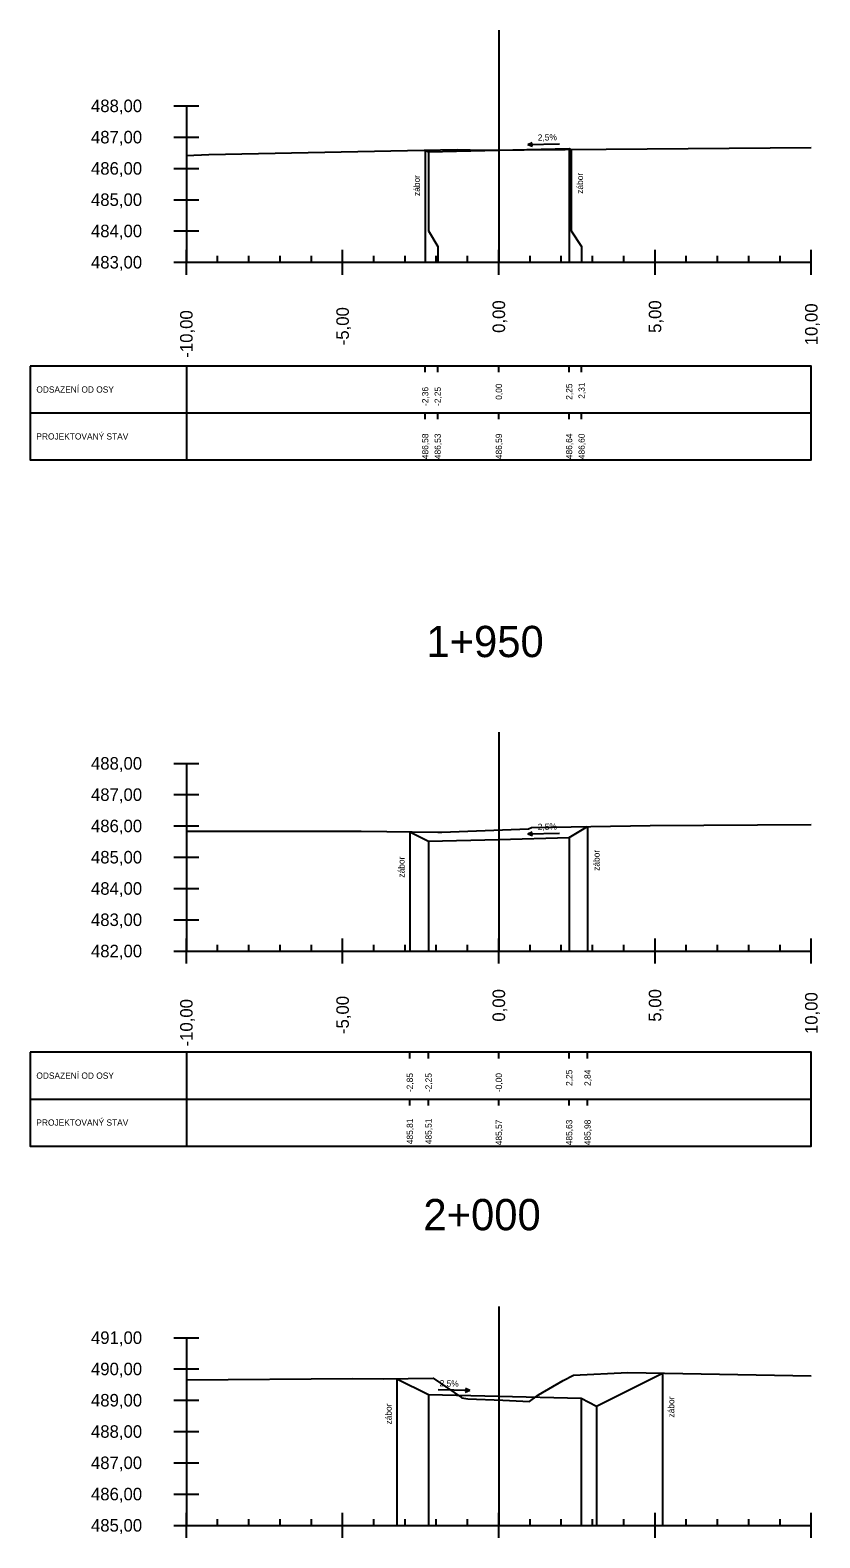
# Model space of a CAD drawing. Extents: x -631407 to -631215, y -1089700 to -1088598.
# Drawn here: x -631285.2 to -631259.93, y -1088856.74 to -1088808.54 of the extents above; entities that cross this region are included whole.
import ezdxf

# ---------------------------------------------------------------- set-up
doc = ezdxf.new("R2010")
doc.units = 0
for name, color, linetype in [('59', 7, 'Continuous'), ('NIVELETA_VYSKY', 7, 'Continuous'), ('REZ_BODY', 7, 'Continuous'), ('REZ_ODSTUPY', 7, 'Continuous'), ('REZ_POPIS', 7, 'Continuous'), ('REZ_RAMY', 7, 'Continuous'), ('REZ_STANICENI', 7, 'Continuous'), ('REZ_SVISLE', 7, 'Continuous'), ('REZ_TENKA', 7, 'Continuous'), ('REZ_TLUSTA', 7, 'Continuous'), ('TABULKA_POPIS', 7, 'Continuous'), ('TEREN', 7, 'Continuous'), ('zábor', 7, 'Continuous')]:
    doc.layers.add(name, color=color, linetype=linetype)

msp = doc.modelspace()

# ---------------------------------------------------------------- linework, layer by layer
at = {"layer": '59'}
for p, q in [((-631280.602, -1088810.959), (-631279.802, -1088810.959)), ((-631280.202, -1088810.959), (-631280.202, -1088815.959)), ((-631280.602, -1088811.959), (-631279.802, -1088811.959)), ((-631280.602, -1088812.959), (-631279.802, -1088812.959)), ((-631280.602, -1088813.959), (-631279.802, -1088813.959)), ((-631280.602, -1088814.959), (-631279.802, -1088814.959)), ((-631280.602, -1088815.959), (-631279.802, -1088815.959)), ((-631280.602, -1088831.981), (-631279.802, -1088831.981)), ((-631280.202, -1088831.981), (-631280.202, -1088837.981)), ((-631280.602, -1088832.981), (-631279.802, -1088832.981)), ((-631280.602, -1088833.981), (-631279.802, -1088833.981)), ((-631280.602, -1088834.981), (-631279.802, -1088834.981)), ((-631280.602, -1088835.981), (-631279.802, -1088835.981)), ((-631280.602, -1088836.981), (-631279.802, -1088836.981)), ((-631280.602, -1088837.981), (-631279.802, -1088837.981)), ((-631280.602, -1088850.343), (-631279.802, -1088850.343)), ((-631280.202, -1088850.343), (-631280.202, -1088856.343)), ((-631280.602, -1088851.343), (-631279.802, -1088851.343)), ((-631280.602, -1088852.343), (-631279.802, -1088852.343)), ((-631280.602, -1088853.343), (-631279.802, -1088853.343)), ((-631280.602, -1088854.343), (-631279.802, -1088854.343)), ((-631280.602, -1088855.343), (-631279.802, -1088855.343)), ((-631280.602, -1088856.343), (-631279.802, -1088856.343))]:
    msp.add_line(p, q, dxfattribs=at)
at = {"layer": 'REZ_RAMY'}
for p, q in [((-631285.202, -1088819.278), (-631285.202, -1088822.278)), ((-631280.202, -1088819.278), (-631280.202, -1088822.278)), ((-631272.558, -1088819.478), (-631272.558, -1088819.278)), ((-631272.158, -1088819.478), (-631272.158, -1088819.278)), ((-631270.202, -1088819.478), (-631270.202, -1088819.278)), ((-631267.952, -1088819.478), (-631267.952, -1088819.278)), ((-631267.552, -1088819.478), (-631267.552, -1088819.278)), ((-631285.202, -1088820.778), (-631260.202, -1088820.778)), ((-631272.558, -1088820.978), (-631272.558, -1088820.778)), ((-631272.158, -1088820.978), (-631272.158, -1088820.778)), ((-631270.202, -1088820.978), (-631270.202, -1088820.778)), ((-631267.952, -1088820.978), (-631267.952, -1088820.778)), ((-631267.552, -1088820.978), (-631267.552, -1088820.778)), ((-631285.202, -1088841.215), (-631285.202, -1088844.215)), ((-631280.202, -1088841.215), (-631280.202, -1088844.215)), ((-631273.05, -1088841.415), (-631273.05, -1088841.215)), ((-631272.452, -1088841.415), (-631272.452, -1088841.215)), ((-631270.202, -1088841.415), (-631270.202, -1088841.215)), ((-631267.952, -1088841.415), (-631267.952, -1088841.215)), ((-631267.362, -1088841.415), (-631267.362, -1088841.215)), ((-631285.202, -1088842.715), (-631260.202, -1088842.715)), ((-631273.05, -1088842.915), (-631273.05, -1088842.715)), ((-631272.452, -1088842.915), (-631272.452, -1088842.715)), ((-631270.202, -1088842.915), (-631270.202, -1088842.715)), ((-631267.952, -1088842.915), (-631267.952, -1088842.715)), ((-631267.362, -1088842.915), (-631267.362, -1088842.715))]:
    msp.add_line(p, q, dxfattribs=at)
for points in [[(-631285.202, -1088819.278), (-631285.202, -1088822.278), (-631260.202, -1088822.278), (-631260.202, -1088819.278)], [(-631285.202, -1088841.215), (-631285.202, -1088844.215), (-631260.202, -1088844.215), (-631260.202, -1088841.215)]]:
    msp.add_lwpolyline(points, close=True, dxfattribs=at)
at = {"layer": 'REZ_SVISLE'}
for points in [[(-631272.558, -1088812.377), (-631272.558, -1088814.959), (-631272.558, -1088815.459), (-631272.558, -1088815.959)], [(-631272.452, -1088812.43), (-631272.452, -1088814.959), (-631272.158, -1088815.459), (-631272.158, -1088815.959)], [(-631270.202, -1088812.374), (-631270.202, -1088814.959), (-631270.202, -1088815.459), (-631270.202, -1088815.959)], [(-631267.952, -1088812.318), (-631267.952, -1088814.959), (-631267.952, -1088815.459), (-631267.952, -1088815.959)], [(-631267.888, -1088812.356), (-631267.888, -1088814.959), (-631267.552, -1088815.459), (-631267.552, -1088815.959)], [(-631267.362, -1088834.002), (-631267.362, -1088836.981), (-631267.362, -1088837.481), (-631267.362, -1088837.981)], [(-631273.05, -1088834.169), (-631273.05, -1088836.981), (-631273.05, -1088837.481), (-631273.05, -1088837.981)], [(-631272.452, -1088834.469), (-631272.452, -1088836.981), (-631272.452, -1088837.481), (-631272.452, -1088837.981)], [(-631270.202, -1088834.412), (-631270.202, -1088836.981), (-631270.202, -1088837.481), (-631270.202, -1088837.981)], [(-631267.952, -1088834.356), (-631267.952, -1088836.981), (-631267.952, -1088837.481), (-631267.952, -1088837.981)], [(-631264.969, -1088851.481), (-631264.969, -1088855.343), (-631264.969, -1088855.843), (-631264.969, -1088856.343)], [(-631273.461, -1088851.655), (-631273.461, -1088855.343), (-631273.461, -1088855.843), (-631273.461, -1088856.343)], [(-631272.452, -1088852.16), (-631272.452, -1088855.343), (-631272.452, -1088855.843), (-631272.452, -1088856.343)], [(-631270.202, -1088852.216), (-631270.202, -1088855.343), (-631270.202, -1088855.843), (-631270.202, -1088856.343)], [(-631267.571, -1088852.282), (-631267.571, -1088855.343), (-631267.571, -1088855.843), (-631267.571, -1088856.343)], [(-631267.071, -1088852.532), (-631267.071, -1088855.343), (-631267.071, -1088855.843), (-631267.071, -1088856.343)]]:
    msp.add_lwpolyline(points, dxfattribs=at)
at = {"layer": 'REZ_TENKA'}
for p, q in [((-631279.202, -1088815.959), (-631279.202, -1088815.759)), ((-631278.202, -1088815.959), (-631278.202, -1088815.759)), ((-631277.202, -1088815.959), (-631277.202, -1088815.759)), ((-631276.202, -1088815.959), (-631276.202, -1088815.759)), ((-631274.202, -1088815.959), (-631274.202, -1088815.759)), ((-631273.202, -1088815.959), (-631273.202, -1088815.759)), ((-631272.202, -1088815.959), (-631272.202, -1088815.759)), ((-631271.202, -1088815.959), (-631271.202, -1088815.759)), ((-631269.202, -1088815.959), (-631269.202, -1088815.759)), ((-631268.202, -1088815.959), (-631268.202, -1088815.759)), ((-631267.202, -1088815.959), (-631267.202, -1088815.759)), ((-631266.202, -1088815.959), (-631266.202, -1088815.759)), ((-631264.202, -1088815.959), (-631264.202, -1088815.759)), ((-631263.202, -1088815.959), (-631263.202, -1088815.759)), ((-631262.202, -1088815.959), (-631262.202, -1088815.759)), ((-631261.202, -1088815.959), (-631261.202, -1088815.759)), ((-631279.202, -1088837.981), (-631279.202, -1088837.781)), ((-631278.202, -1088837.981), (-631278.202, -1088837.781)), ((-631277.202, -1088837.981), (-631277.202, -1088837.781)), ((-631276.202, -1088837.981), (-631276.202, -1088837.781)), ((-631274.202, -1088837.981), (-631274.202, -1088837.781)), ((-631273.202, -1088837.981), (-631273.202, -1088837.781)), ((-631272.202, -1088837.981), (-631272.202, -1088837.781)), ((-631271.202, -1088837.981), (-631271.202, -1088837.781)), ((-631269.202, -1088837.981), (-631269.202, -1088837.781)), ((-631268.202, -1088837.981), (-631268.202, -1088837.781)), ((-631267.202, -1088837.981), (-631267.202, -1088837.781)), ((-631266.202, -1088837.981), (-631266.202, -1088837.781)), ((-631264.202, -1088837.981), (-631264.202, -1088837.781)), ((-631263.202, -1088837.981), (-631263.202, -1088837.781)), ((-631262.202, -1088837.981), (-631262.202, -1088837.781)), ((-631261.202, -1088837.981), (-631261.202, -1088837.781)), ((-631279.202, -1088856.343), (-631279.202, -1088856.143)), ((-631278.202, -1088856.343), (-631278.202, -1088856.143)), ((-631277.202, -1088856.343), (-631277.202, -1088856.143)), ((-631276.202, -1088856.343), (-631276.202, -1088856.143)), ((-631274.202, -1088856.343), (-631274.202, -1088856.143)), ((-631273.202, -1088856.343), (-631273.202, -1088856.143)), ((-631272.202, -1088856.343), (-631272.202, -1088856.143)), ((-631271.202, -1088856.343), (-631271.202, -1088856.143)), ((-631269.202, -1088856.343), (-631269.202, -1088856.143)), ((-631268.202, -1088856.343), (-631268.202, -1088856.143)), ((-631267.202, -1088856.343), (-631267.202, -1088856.143)), ((-631266.202, -1088856.343), (-631266.202, -1088856.143)), ((-631264.202, -1088856.343), (-631264.202, -1088856.143)), ((-631263.202, -1088856.343), (-631263.202, -1088856.143)), ((-631262.202, -1088856.343), (-631262.202, -1088856.143)), ((-631261.202, -1088856.343), (-631261.202, -1088856.143))]:
    msp.add_line(p, q, dxfattribs=at)
at = {"layer": 'REZ_TLUSTA'}
for p, q in [((-631270.202, -1088808.539), (-631270.202, -1088815.959)), ((-631280.202, -1088816.359), (-631280.202, -1088815.559)), ((-631275.202, -1088816.359), (-631275.202, -1088815.559)), ((-631270.202, -1088816.359), (-631270.202, -1088815.559)), ((-631265.202, -1088816.359), (-631265.202, -1088815.559)), ((-631260.202, -1088816.359), (-631260.202, -1088815.559)), ((-631280.202, -1088815.959), (-631260.202, -1088815.959)), ((-631270.202, -1088830.981), (-631270.202, -1088837.981)), ((-631280.202, -1088838.381), (-631280.202, -1088837.581)), ((-631280.202, -1088837.981), (-631260.202, -1088837.981)), ((-631275.202, -1088838.381), (-631275.202, -1088837.581)), ((-631270.202, -1088838.381), (-631270.202, -1088837.581)), ((-631265.202, -1088838.381), (-631265.202, -1088837.581)), ((-631260.202, -1088838.381), (-631260.202, -1088837.581)), ((-631270.202, -1088849.343), (-631270.202, -1088856.343)), ((-631280.202, -1088856.743), (-631280.202, -1088855.943)), ((-631275.202, -1088856.743), (-631275.202, -1088855.943)), ((-631270.202, -1088856.743), (-631270.202, -1088855.943)), ((-631265.202, -1088856.743), (-631265.202, -1088855.943)), ((-631260.202, -1088856.743), (-631260.202, -1088855.943)), ((-631280.202, -1088856.343), (-631260.202, -1088856.343))]:
    msp.add_line(p, q, dxfattribs=at)
at = {"layer": 'TEREN'}
for points in [[(-631280.202, -1088812.543), (-631279.485, -1088812.517), (-631271.539, -1088812.356), (-631270.703, -1088812.379), (-631260.202, -1088812.292)], [(-631272.558, -1088812.377), (-631272.452, -1088812.43), (-631270.202, -1088812.374), (-631267.952, -1088812.318), (-631267.888, -1088812.356)], [(-631280.202, -1088834.15), (-631274.604, -1088834.154), (-631272.159, -1088834.178), (-631272.021, -1088834.176), (-631269.252, -1088834.078), (-631269.16, -1088834.037), (-631265.359, -1088833.964), (-631260.202, -1088833.938)], [(-631273.05, -1088834.169), (-631272.452, -1088834.469), (-631270.202, -1088834.412), (-631267.952, -1088834.356), (-631267.362, -1088834.002)], [(-631280.202, -1088851.694), (-631274.871, -1088851.648), (-631273.902, -1088851.662), (-631272.299, -1088851.639), (-631271.399, -1088852.26), (-631271.385, -1088852.267), (-631271.189, -1088852.299), (-631270.07, -1088852.34), (-631269.224, -1088852.379), (-631268.976, -1088852.202), (-631268.927, -1088852.171), (-631268.138, -1088851.709), (-631267.808, -1088851.541), (-631266.076, -1088851.461), (-631260.202, -1088851.567)], [(-631273.461, -1088851.655), (-631272.452, -1088852.16), (-631270.202, -1088852.216), (-631267.571, -1088852.282), (-631267.071, -1088852.532), (-631264.969, -1088851.481)]]:
    msp.add_lwpolyline(points, dxfattribs=at)
at = {"layer": 'zábor'}
for p, q in [((-631269.269, -1088812.194), (-631269.132, -1088812.13)), ((-631269.269, -1088812.194), (-631268.261, -1088812.169)), ((-631269.269, -1088812.194), (-631269.129, -1088812.252)), ((-631269.269, -1088834.233), (-631269.132, -1088834.168)), ((-631269.269, -1088834.233), (-631268.261, -1088834.208)), ((-631269.269, -1088834.233), (-631269.129, -1088834.291)), ((-631271.135, -1088852.037), (-631272.143, -1088852.012)), ((-631271.135, -1088852.037), (-631271.274, -1088852.095)), ((-631271.135, -1088852.037), (-631271.271, -1088851.972))]:
    msp.add_line(p, q, dxfattribs=at)

# ---------------------------------------------------------------- texts
at = {"layer": 'NIVELETA_VYSKY'}
for s, p in [('486,58', (-631272.458, -1088822.254)), ('486,53', (-631272.058, -1088822.254)), ('486,59', (-631270.102, -1088822.254)), ('486,64', (-631267.852, -1088822.254)), ('486,60', (-631267.452, -1088822.254)), ('485,81', (-631272.95, -1088844.157)), ('485,51', (-631272.352, -1088844.157)), ('485,57', (-631270.102, -1088844.191)), ('485,63', (-631267.852, -1088844.191)), ('485,98', (-631267.262, -1088844.191))]:
    msp.add_text(s, height=0.2, rotation=90, dxfattribs=at).set_placement(p)
at = {"layer": 'REZ_BODY'}
for s, p in [('-2,36', (-631272.458, -1088820.555)), ('-2,25', (-631272.058, -1088820.555)), ('0,00', (-631270.102, -1088820.357)), ('2,25', (-631267.852, -1088820.357)), ('2,31', (-631267.452, -1088820.324)), ('2,25', (-631267.852, -1088842.294)), ('2,84', (-631267.262, -1088842.294)), ('-2,85', (-631272.95, -1088842.492)), ('-2,25', (-631272.352, -1088842.492)), ('-0,00', (-631270.102, -1088842.492))]:
    msp.add_text(s, height=0.2, rotation=90, dxfattribs=at).set_placement(p)
at = {"layer": 'REZ_ODSTUPY'}
for s, p in [('0,00', (-631270.002, -1088818.218)), ('5,00', (-631265.002, -1088818.218)), ('-10,00', (-631280.002, -1088819.011)), ('-5,00', (-631275.002, -1088818.614)), ('10,00', (-631260.002, -1088818.614)), ('0,00', (-631270.002, -1088840.239)), ('5,00', (-631265.002, -1088840.239)), ('10,00', (-631260.002, -1088840.636)), ('-10,00', (-631280.002, -1088841.033)), ('-5,00', (-631275.002, -1088840.636))]:
    msp.add_text(s, height=0.4, rotation=90, dxfattribs=at).set_placement(p)
at = {"layer": 'REZ_POPIS'}
for s, p in [('488,00', (-631283.254, -1088811.159)), ('487,00', (-631283.254, -1088812.159)), ('486,00', (-631283.254, -1088813.159)), ('485,00', (-631283.254, -1088814.159)), ('484,00', (-631283.254, -1088815.159)), ('483,00', (-631283.254, -1088816.159)), ('488,00', (-631283.254, -1088832.181)), ('487,00', (-631283.254, -1088833.181)), ('486,00', (-631283.254, -1088834.181)), ('485,00', (-631283.254, -1088835.181)), ('484,00', (-631283.254, -1088836.181)), ('483,00', (-631283.254, -1088837.181)), ('482,00', (-631283.254, -1088838.181)), ('491,00', (-631283.254, -1088850.543)), ('490,00', (-631283.254, -1088851.543)), ('489,00', (-631283.254, -1088852.543)), ('488,00', (-631283.254, -1088853.543)), ('487,00', (-631283.254, -1088854.543)), ('486,00', (-631283.254, -1088855.543)), ('485,00', (-631283.254, -1088856.543))]:
    msp.add_text(s, height=0.4, dxfattribs=at).set_placement(p)
at = {"layer": 'REZ_STANICENI'}
for s, p in [('1+950', (-631272.52, -1088828.584)), ('2+000', (-631272.616, -1088846.909))]:
    msp.add_text(s, height=1, dxfattribs=at).set_placement(p)
at = {"layer": 'TABULKA_POPIS'}
for s, p in [('ODSAZENÍ OD OSY', (-631285.002, -1088820.128)), ('PROJEKTOVANÝ STAV', (-631285.002, -1088821.628)), ('ODSAZENÍ OD OSY', (-631285.002, -1088842.065)), ('PROJEKTOVANÝ STAV', (-631285.002, -1088843.565))]:
    msp.add_text(s, height=0.2, dxfattribs=at).set_placement(p)
at = {"layer": 'zábor'}
for s, rotation, p in [('2,5%', 1.4321, (-631268.952, -1088812.074)), ('zábor', 90, (-631272.728, -1088813.841)), ('zábor', 90, (-631267.505, -1088813.77)), ('2,5%', 1.4321, (-631268.952, -1088834.112)), ('zábor', 90, (-631273.22, -1088835.633)), ('zábor', 90, (-631266.979, -1088835.417)), ('2,5%', 358.5679, (-631272.099, -1088851.9)), ('zábor', 90, (-631264.586, -1088852.896)), ('zábor', 90, (-631273.632, -1088853.119))]:
    msp.add_text(s, height=0.2, rotation=rotation, dxfattribs=at).set_placement(p)

doc.saveas('drawing.dxf')
